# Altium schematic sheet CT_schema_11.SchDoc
size 147 x 119 mm
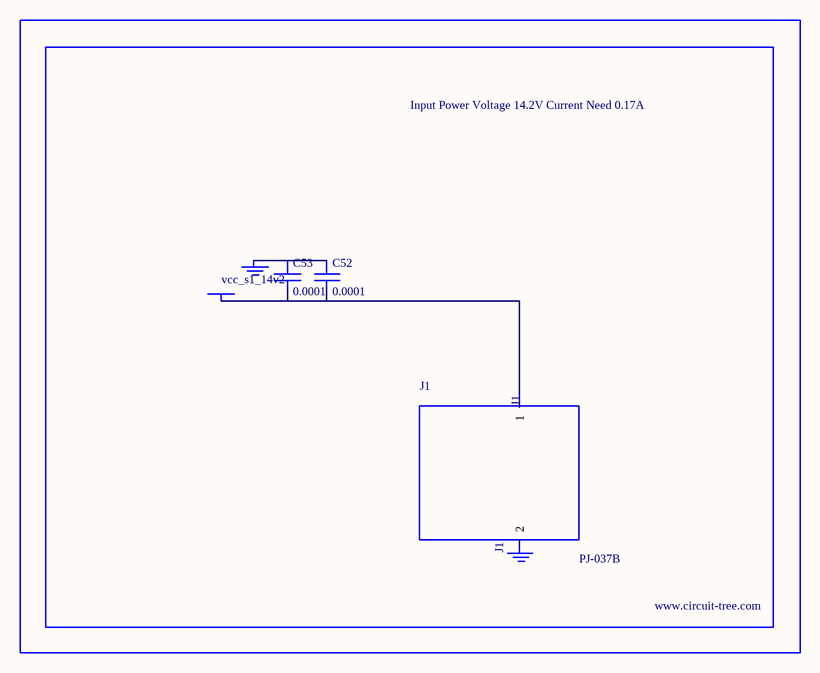
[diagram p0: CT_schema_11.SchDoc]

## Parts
BORDER10  (no value)
C52  0.0001  [EXV-9H]
C53  0.0001  [EXV-9H]
GND_INSTANCE_10_0  (no value)
GND_INSTANCE_10_1  (no value)
J1  PJ-037B  [PJ-037B_PACKAGE]
POWER_INSTANCE_10_0  vcc_s1_14v2

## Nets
NetC52_1: C52.1 C53.1 GND_INSTANCE_10_0.0(GND)
NetC52_2: C52.2 C53.2 J1.1 POWER_INSTANCE_10_0.0(PWR)

Not connected (* = marked no-connect by the designer): GND_INSTANCE_10_1 0(GND); J1 2

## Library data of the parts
BORDER10 = BORDER_PAGE10
C52 C53 = EDK107M035A9HAA
GND_INSTANCE_10_0 GND_INSTANCE_10_1 = GND
POWER_INSTANCE_10_0 = PWR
